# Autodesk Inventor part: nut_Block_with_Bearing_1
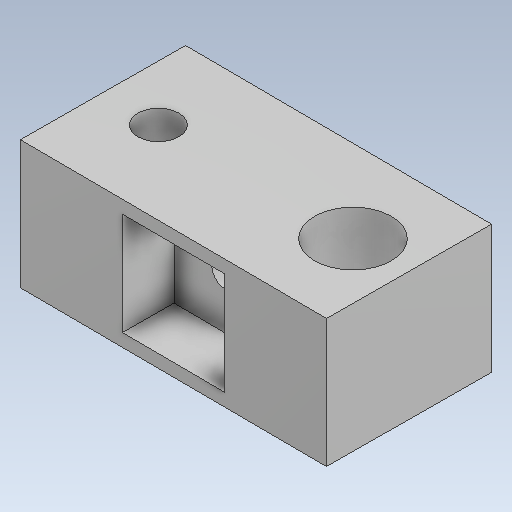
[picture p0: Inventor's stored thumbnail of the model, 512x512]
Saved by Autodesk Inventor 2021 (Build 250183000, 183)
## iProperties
Created: 2026-10
Part Number: nut_Block_with_Bearing_1
Material: Generic
Document SubType Name: Modeling
Designer: hp
Density: 1 g/cm^3
Appearance: Default
Author: hp
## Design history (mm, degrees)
feature "Body1"
body "Solid1"
